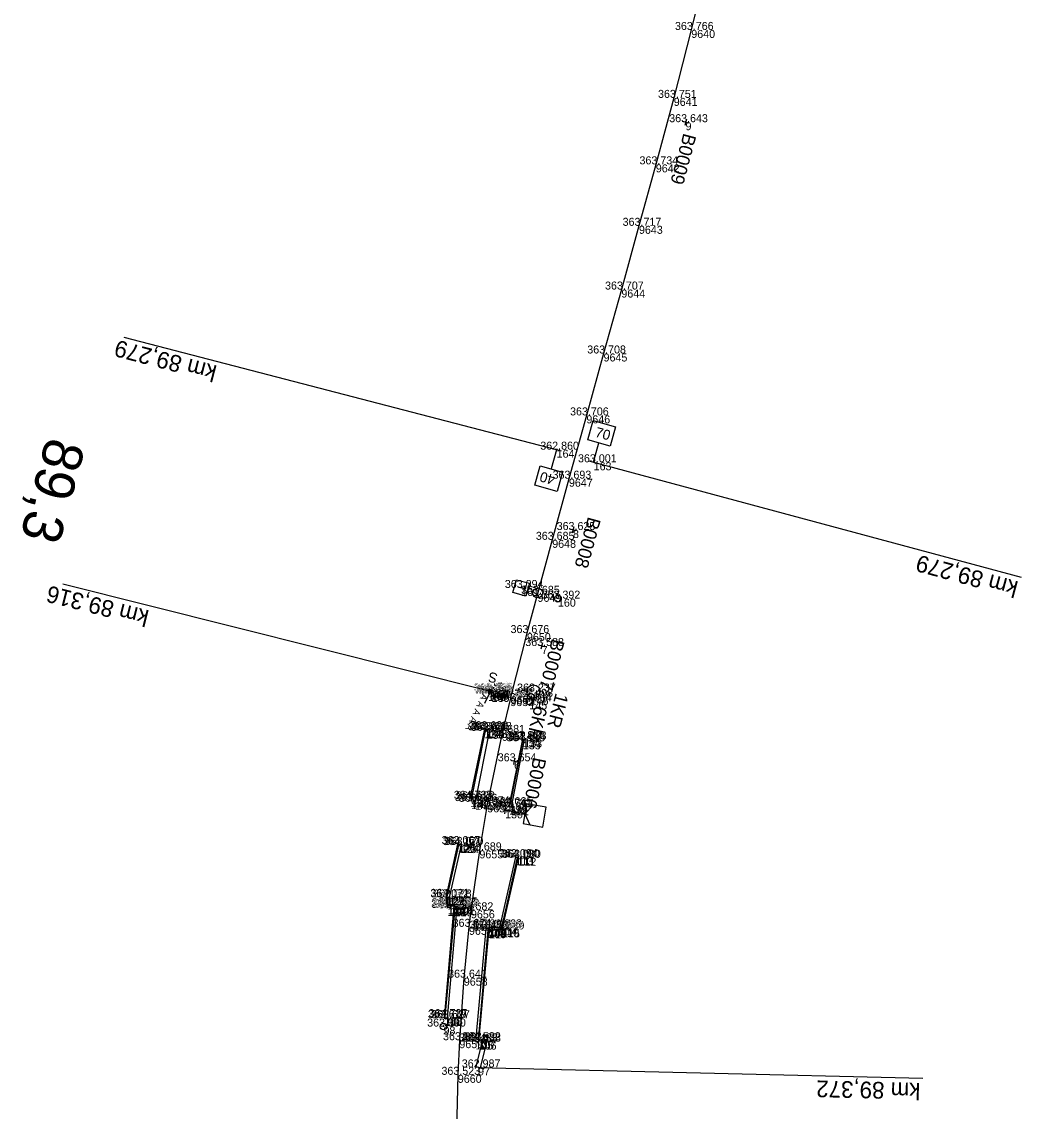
# Model space of a CAD drawing. Extents: x -599511 to -595511, y -1067427 to -1062061.
# Drawn here: x -595742.8 to -595592.8, y -1067096.5 to -1066933.1 of the extents above; entities that cross this region are included whole.
import ezdxf

# ---------------------------------------------------------------- set-up
doc = ezdxf.new("R2010")
doc.units = 0
for name, color, linetype in [('Vrstva 1', 7, 'Continuous'), ('Vrstva 12', 7, 'Continuous'), ('Vrstva 17', 7, 'Continuous'), ('Vrstva 18', 7, 'Continuous'), ('Vrstva 27', 7, 'Continuous'), ('Vrstva 33', 7, 'Continuous'), ('Vrstva 43', 7, 'Continuous'), ('Vrstva 49', 7, 'Continuous'), ('Vrstva 5', 7, 'Continuous'), ('Vrstva 50', 7, 'Continuous'), ('Vrstva 6', 7, 'Continuous'), ('Vrstva 60', 7, 'Continuous'), ('Vrstva 61', 7, 'Continuous'), ('Vrstva 7', 7, 'Continuous')]:
    doc.layers.add(name, color=color, linetype=linetype)

msp = doc.modelspace()

# ---------------------------------------------------------------- linework, layer by layer
at = {"layer": 'Vrstva 1'}
msp.add_lwpolyline([(-595640.14, -1066925.35), (-595642.33, -1066934.34), (-595644.96, -1066944.53), (-595647.65, -1066954.5), (-595650.18, -1066963.72), (-595652.82, -1066973.28), (-595655.49, -1066982.87), (-595658.07, -1066992.16), (-595660.69, -1067001.65), (-595663.2, -1067010.82), (-595665.41, -1067018.92), (-595666.99, -1067024.81), (-595669.42, -1067034.28), (-595669.48, -1067034.56), (-595670.73, -1067039.78), (-595672.94, -1067050.5), (-595674.12, -1067057.4), (-595675.39, -1067066.39), (-595675.69, -1067068.87), (-595676.46, -1067076.5), (-595677.13, -1067085.88), (-595677.36, -1067091.07), (-595677.54, -1067099.36)], dxfattribs=at)
at = {"layer": 'Vrstva 12'}
for p, q in [((-595672.83, -1067033.8), (-595672.83, -1067033.8)), ((-595672.7, -1067033.24), (-595672.7, -1067033.24)), ((-595672.14, -1067033.37), (-595672.14, -1067033.37)), ((-595672.29, -1067033.93), (-595672.28, -1067033.93))]:
    msp.add_line(p, q, dxfattribs=at)
for points in [[(-595672.7, -1067033.24), (-595672.83, -1067033.8), (-595672.28, -1067033.93), (-595672.14, -1067033.37)], [(-595672.7, -1067033.24), (-595672.83, -1067033.8), (-595672.29, -1067033.93), (-595672.14, -1067033.37)]]:
    msp.add_lwpolyline(points, close=True, dxfattribs=at)
at = {"layer": 'Vrstva 17'}
for p, q in [((-595669.51, -1067050.63), (-595667.6, -1067041.04)), ((-595677.83, -1067066.09), (-595679.29, -1067082.42)), ((-595678.84, -1067065.79), (-595677.76, -1067065.66)), ((-595674.28, -1067085.88), (-595672.79, -1067069.37))]:
    msp.add_line(p, q, dxfattribs=at)
for points in [[(-595675.16, -1067049.76), (-595675.51, -1067049.67), (-595673.38, -1067039.4), (-595673.04, -1067039.47)], [(-595677.25, -1067056.61), (-595679, -1067064.38), (-595678.84, -1067065.79)], [(-595672.79, -1067069.31), (-595670.83, -1067069.2), (-595668.43, -1067058.47)]]:
    msp.add_lwpolyline(points, dxfattribs=at)
at = {"layer": 'Vrstva 18'}
for p, q in [((-595673.15, -1067069.15), (-595674.72, -1067086.07)), ((-595674.23, -1067086.09), (-595672.68, -1067069.19)), ((-595672.68, -1067069.19), (-595673.15, -1067069.15)), ((-595674.72, -1067086.07), (-595674.23, -1067086.09))]:
    msp.add_line(p, q, dxfattribs=at)
for points in [[(-595673.15, -1067039.23), (-595672.61, -1067039.34), (-595674.77, -1067050.12), (-595675.34, -1067050.01)], [(-595669.67, -1067050.83), (-595667.62, -1067040.71), (-595667.4, -1067040.76), (-595669.36, -1067050.94)], [(-595677.34, -1067056.46), (-595676.88, -1067056.58), (-595678.65, -1067064.45), (-595678.44, -1067065.97), (-595678.9, -1067066.03), (-595679.12, -1067064.45)], [(-595679.41, -1067082.55), (-595678.91, -1067082.58), (-595677.47, -1067065.86), (-595677.94, -1067065.82)]]:
    msp.add_lwpolyline(points, close=True, dxfattribs=at)
msp.add_lwpolyline([(-595672.64, -1067069.43), (-595670.72, -1067069.26), (-595668.26, -1067058.52), (-595668.73, -1067058.42), (-595671.09, -1067068.95), (-595672.65, -1067068.99), (-595672.64, -1067069.43)], dxfattribs=at)
at = {"layer": 'Vrstva 27'}
for p, q in [((-595666.62, -1067035), (-595666.64, -1067035.1)), ((-595666.42, -1067034.32), (-595666.44, -1067034.41))]:
    msp.add_line(p, q, dxfattribs=at)
for centre in [(-595666.63, -1067035.05), (-595666.43, -1067034.37)]:
    msp.add_circle(centre, 0.5, dxfattribs=at)
at = {"layer": 'Vrstva 33'}
for p, q in [((-595667.38, -1067018.17), (-595668.35, -1067017.91)), ((-595667.25, -1067017.69), (-595667.51, -1067018.65))]:
    msp.add_line(p, q, dxfattribs=at)
msp.add_lwpolyline([(-595666.63, -1067017.34), (-595667.16, -1067019.27), (-595669.09, -1067018.74), (-595668.56, -1067016.81), (-595666.63, -1067017.34)], dxfattribs=at)
at = {"layer": 'Vrstva 43'}
msp.add_circle((-595666.02, -1067033.58), 1, dxfattribs=at)
at = {"layer": 'Vrstva 49'}
for p, q in [((-595672.21, -1067033.46), (-595672.63, -1067033.72)), ((-595672.55, -1067033.38), (-595672.29, -1067033.8))]:
    msp.add_line(p, q, dxfattribs=at)
at = {"layer": 'Vrstva 5'}
for p, q in [((-595662.54, -1066997.3), (-595727.44, -1066980.47)), ((-595662.54, -1066997.3), (-595663.34, -1067000.19)), ((-595661.81, -1066997.5), (-595663.26, -1066997.1)), ((-595656.98, -1066999.19), (-595656.18, -1066996.29)), ((-595657.7, -1066998.99), (-595656.25, -1066999.39)), ((-595656.98, -1066999.19), (-595592.82, -1067016.44))]:
    msp.add_line(p, q, dxfattribs=at)
for points in [[(-595654.49, -1066996.76), (-595657.86, -1066995.83), (-595657.07, -1066992.94), (-595653.69, -1066993.87)], [(-595665.02, -1066999.73), (-595661.65, -1067000.66), (-595662.45, -1067003.55), (-595665.82, -1067002.62)]]:
    msp.add_lwpolyline(points, close=True, dxfattribs=at)
at = {"layer": 'Vrstva 50'}
msp.add_line((-595679.5, -1067083.78), (-595679.51, -1067083.88), dxfattribs=at)
msp.add_circle((-595679.51, -1067083.83), 0.5, dxfattribs=at)
at = {"layer": 'Vrstva 6'}
for p, q in [((-595672.48, -1067033.55), (-595736.65, -1067017.48)), ((-595673.33, -1067035.34), (-595672.48, -1067033.55)), ((-595672.03, -1067033.77), (-595672.94, -1067033.34)), ((-595673.18, -1067086.66), (-595673.62, -1067085.94)), ((-595673.05, -1067086.15), (-595673.49, -1067085.42)), ((-595672.92, -1067085.63), (-595673.26, -1067085.08)), ((-595673.86, -1067086.99), (-595673.88, -1067086.96)), ((-595673.35, -1067087.11), (-595673.75, -1067086.45)), ((-595674.32, -1067089.96), (-595607.59, -1067091.59)), ((-595674.03, -1067090.04), (-595673.45, -1067090.18))]:
    msp.add_line(p, q, dxfattribs=at)
msp.add_lwpolyline([(-595674.61, -1067089.89), (-595673.39, -1067085.04), (-595672.81, -1067085.19), (-595674.03, -1067090.04), (-595674.61, -1067089.89)], dxfattribs=at)
msp.add_lwpolyline([(-595672.81, -1067085.19), (-595673.3, -1067087.13), (-595673.88, -1067086.98), (-595673.39, -1067085.04)], close=True, dxfattribs=at)
at = {"layer": 'Vrstva 60'}
for p, q in [((-595642.33, -1066934.34), (-595642.33, -1066934.34)), ((-595644.96, -1066944.53), (-595644.96, -1066944.53)), ((-595643.19, -1066948.18), (-595643.19, -1066948.18)), ((-595647.65, -1066954.5), (-595647.65, -1066954.5)), ((-595650.18, -1066963.72), (-595650.18, -1066963.72)), ((-595652.82, -1066973.28), (-595652.82, -1066973.28)), ((-595655.49, -1066982.87), (-595655.49, -1066982.87)), ((-595658.07, -1066992.16), (-595658.07, -1066992.16)), ((-595662.54, -1066997.3), (-595662.54, -1066997.3)), ((-595656.98, -1066999.19), (-595656.98, -1066999.19)), ((-595660.69, -1067001.65), (-595660.69, -1067001.65)), ((-595663.2, -1067010.82), (-595663.2, -1067010.82)), ((-595660.08, -1067009.35), (-595660.08, -1067009.35)), ((-595667.86, -1067018.04), (-595667.86, -1067018.04)), ((-595665.41, -1067018.92), (-595665.41, -1067018.92)), ((-595662.34, -1067019.65), (-595662.34, -1067019.65)), ((-595666.99, -1067024.81), (-595666.99, -1067024.81)), ((-595664.78, -1067026.75), (-595664.78, -1067026.75)), ((-595672.83, -1067033.8), (-595672.83, -1067033.8)), ((-595672.83, -1067033.8), (-595672.83, -1067033.8)), ((-595672.7, -1067033.24), (-595672.7, -1067033.24)), ((-595672.7, -1067033.24), (-595672.7, -1067033.24)), ((-595672.48, -1067033.55), (-595672.48, -1067033.55)), ((-595672.42, -1067033.59), (-595672.42, -1067033.59)), ((-595672.14, -1067033.37), (-595672.14, -1067033.37)), ((-595672.14, -1067033.37), (-595672.14, -1067033.37)), ((-595666.02, -1067033.58), (-595666.02, -1067033.58)), ((-595672.29, -1067033.93), (-595672.29, -1067033.93)), ((-595672.28, -1067033.93), (-595672.28, -1067033.93)), ((-595669.48, -1067034.56), (-595669.48, -1067034.56)), ((-595669.42, -1067034.28), (-595669.42, -1067034.28)), ((-595666.63, -1067035.05), (-595666.63, -1067035.05)), ((-595666.43, -1067034.37), (-595666.43, -1067034.37)), ((-595673.38, -1067039.4), (-595673.38, -1067039.4)), ((-595673.15, -1067039.23), (-595673.15, -1067039.23)), ((-595673.04, -1067039.47), (-595673.04, -1067039.47)), ((-595672.61, -1067039.34), (-595672.61, -1067039.34)), ((-595670.73, -1067039.78), (-595670.73, -1067039.78)), ((-595667.62, -1067040.71), (-595667.62, -1067040.71)), ((-595667.6, -1067041.04), (-595667.6, -1067041.04)), ((-595667.4, -1067040.76), (-595667.4, -1067040.76)), ((-595668.92, -1067044.04), (-595668.92, -1067044.04)), ((-595675.51, -1067049.67), (-595675.51, -1067049.67)), ((-595675.34, -1067050.01), (-595675.34, -1067050.01)), ((-595675.16, -1067049.76), (-595675.16, -1067049.76)), ((-595674.77, -1067050.12), (-595674.77, -1067050.12)), ((-595672.94, -1067050.5), (-595672.94, -1067050.5)), ((-595670.27, -1067051.4), (-595670.27, -1067051.4)), ((-595669.67, -1067050.83), (-595669.67, -1067050.83)), ((-595669.51, -1067050.63), (-595669.51, -1067050.63)), ((-595669.36, -1067050.94), (-595669.36, -1067050.94)), ((-595677.34, -1067056.46), (-595677.34, -1067056.46)), ((-595677.25, -1067056.61), (-595677.25, -1067056.61)), ((-595676.88, -1067056.58), (-595676.88, -1067056.58)), ((-595674.12, -1067057.4), (-595674.12, -1067057.4)), ((-595668.73, -1067058.42), (-595668.73, -1067058.42)), ((-595668.43, -1067058.47), (-595668.43, -1067058.47)), ((-595668.26, -1067058.52), (-595668.26, -1067058.52)), ((-595679.12, -1067064.45), (-595679.12, -1067064.45)), ((-595679, -1067064.38), (-595679, -1067064.38)), ((-595678.65, -1067064.45), (-595678.65, -1067064.45)), ((-595678.9, -1067066.03), (-595678.9, -1067066.03)), ((-595678.84, -1067065.79), (-595678.84, -1067065.79)), ((-595678.44, -1067065.97), (-595678.44, -1067065.97)), ((-595677.94, -1067065.82), (-595677.94, -1067065.82)), ((-595677.83, -1067066.09), (-595677.83, -1067066.09)), ((-595677.76, -1067065.66), (-595677.76, -1067065.66)), ((-595677.47, -1067065.86), (-595677.47, -1067065.86)), ((-595675.39, -1067066.39), (-595675.39, -1067066.39)), ((-595675.69, -1067068.87), (-595675.69, -1067068.87)), ((-595673.15, -1067069.15), (-595673.15, -1067069.15)), ((-595672.79, -1067069.31), (-595672.79, -1067069.31)), ((-595672.79, -1067069.37), (-595672.79, -1067069.37)), ((-595672.68, -1067069.19), (-595672.68, -1067069.19)), ((-595672.65, -1067068.99), (-595672.65, -1067068.99)), ((-595672.64, -1067069.43), (-595672.64, -1067069.43)), ((-595671.09, -1067068.95), (-595671.09, -1067068.95)), ((-595670.83, -1067069.2), (-595670.83, -1067069.2)), ((-595670.72, -1067069.26), (-595670.72, -1067069.26)), ((-595676.46, -1067076.5), (-595676.46, -1067076.5)), ((-595679.41, -1067082.55), (-595679.41, -1067082.55)), ((-595679.29, -1067082.42), (-595679.29, -1067082.42)), ((-595678.91, -1067082.58), (-595678.91, -1067082.58)), ((-595679.51, -1067083.83), (-595679.51, -1067083.83)), ((-595677.13, -1067085.88), (-595677.13, -1067085.88)), ((-595674.72, -1067086.07), (-595674.72, -1067086.07)), ((-595674.28, -1067085.88), (-595674.28, -1067085.88)), ((-595674.23, -1067086.09), (-595674.23, -1067086.09)), ((-595674.32, -1067089.96), (-595674.32, -1067089.96)), ((-595677.36, -1067091.07), (-595677.36, -1067091.07))]:
    msp.add_line(p, q, dxfattribs=at)
at = {"layer": 'Vrstva 7'}
for p, q in [((-595642.71, -1066948.31), (-595643.67, -1066948.05)), ((-595643.06, -1066947.7), (-595643.32, -1066948.66)), ((-595659.6, -1067009.48), (-595660.56, -1067009.22)), ((-595659.95, -1067008.87), (-595660.21, -1067009.83)), ((-595662.33, -1067019.6), (-595662.35, -1067019.7)), ((-595664.3, -1067026.87), (-595665.27, -1067026.63)), ((-595664.66, -1067026.26), (-595664.91, -1067027.23)), ((-595668.82, -1067043.55), (-595669.02, -1067044.53)), ((-595668.43, -1067044.15), (-595669.41, -1067043.94)), ((-595670.19, -1067050.91), (-595670.35, -1067051.9)), ((-595667.31, -1067051.91), (-595670.27, -1067051.4))]:
    msp.add_line(p, q, dxfattribs=at)
for points in [[(-595667.31, -1067051.91), (-595667.57, -1067053.39), (-595664.61, -1067053.9), (-595664.1, -1067050.94), (-595667.06, -1067050.43), (-595667.31, -1067051.91)], [(-595666.07, -1067050.6), (-595667.31, -1067051.91), (-595666.58, -1067053.56)]]:
    msp.add_lwpolyline(points, dxfattribs=at)
for centre, radius in [((-595665.38, -1067018.79), 0.75), ((-595662.34, -1067019.65), 0.5)]:
    msp.add_circle(centre, radius, dxfattribs=at)

# ---------------------------------------------------------------- texts
at = {"layer": 'Vrstva 27'}
for s, rotation, p in [('1KR', 255.6438, (-595662.67, -1067033.7)), ('6KR', 256.6208, (-595665.85, -1067035.63))]:
    msp.add_text(s, height=2, rotation=rotation, dxfattribs=at).set_placement(p)
at = {"layer": 'Vrstva 5'}
for s, height, rotation, p in [('km 89,279', 2.5, 165.4618, (-595713.36, -1066984.72)), ('70', 1.5, 344.5811, (-595656.86, -1066995.33)), ('40', 1.5, 164.5811, (-595662.65, -1067001.16)), ('km 89,279', 2.5, 164.9478, (-595593.11, -1067017.1))]:
    msp.add_text(s, height=height, rotation=rotation, dxfattribs=at).set_placement(p)
at = {"layer": 'Vrstva 6'}
for s, height, rotation, p in [('km 89,316', 2.5, 165.9379, (-595723.55, -1067021.44)), ('S', 1.5, 166.6122, (-595671.28, -1067030.92)), ('  A A A A A ', 1, 244.7434, (-595673.39, -1067033.13)), ('km 89,372', 2.5, 178.6042, (-595607.93, -1067092.29))]:
    msp.add_text(s, height=height, rotation=rotation, dxfattribs=at).set_placement(p)
at = {"layer": 'Vrstva 60'}
for s, p in [('9640', (-595642.33, -1066935.54)), ('9641', (-595644.96, -1066945.73)), ('9', (-595643.19, -1066949.38)), ('9642', (-595647.65, -1066955.7)), ('9643', (-595650.18, -1066964.92)), ('9644', (-595652.82, -1066974.48)), ('9645', (-595655.49, -1066984.07)), ('9646', (-595658.07, -1066993.35)), ('164', (-595662.54, -1066998.5)), ('163', (-595656.98, -1067000.39)), ('9647', (-595660.69, -1067002.85)), ('8', (-595660.08, -1067010.55)), ('9648', (-595663.2, -1067012.02)), ('161', (-595667.86, -1067019.24)), ('9649', (-595665.41, -1067020.12)), ('160', (-595662.34, -1067020.85)), ('9650', (-595666.99, -1067026.01)), ('7', (-595664.78, -1067027.95)), ('156', (-595672.83, -1067035)), ('155', (-595672.83, -1067035)), ('154', (-595672.7, -1067034.44)), ('153', (-595672.7, -1067034.44)), ('157', (-595672.48, -1067034.75)), ('158', (-595672.42, -1067034.79)), ('152', (-595672.14, -1067034.57)), ('151', (-595672.14, -1067034.57)), ('148', (-595666.02, -1067034.78)), ('149', (-595672.29, -1067035.13)), ('150', (-595672.28, -1067035.13)), ('9652', (-595669.48, -1067035.76)), ('9651', (-595669.42, -1067035.48)), ('145', (-595666.63, -1067036.25)), ('146', (-595666.43, -1067035.57)), ('138', (-595673.38, -1067040.6)), ('144', (-595673.15, -1067040.43)), ('139', (-595673.04, -1067040.67)), ('143', (-595672.61, -1067040.54)), ('9653', (-595670.73, -1067040.98)), ('134', (-595667.62, -1067041.91)), ('135', (-595667.6, -1067042.24)), ('133', (-595667.4, -1067041.96)), ('6', (-595668.92, -1067045.24)), ('137', (-595675.51, -1067050.87)), ('142', (-595675.34, -1067051.21)), ('140', (-595675.16, -1067050.96)), ('141', (-595674.77, -1067051.32)), ('9654', (-595672.94, -1067051.7)), ('130', (-595670.27, -1067052.6)), ('132', (-595669.67, -1067052.03)), ('136', (-595669.51, -1067051.83)), ('131', (-595669.36, -1067052.14)), ('125', (-595677.34, -1067057.66)), ('123', (-595677.25, -1067057.81)), ('124', (-595676.88, -1067057.78)), ('9655', (-595674.12, -1067058.6)), ('113', (-595668.73, -1067059.62)), ('111', (-595668.43, -1067059.67)), ('112', (-595668.26, -1067059.72)), ('127', (-595679.12, -1067065.65)), ('122', (-595679, -1067065.58)), ('126', (-595678.65, -1067065.65)), ('128', (-595678.9, -1067067.23)), ('121', (-595678.84, -1067066.99)), ('129', (-595678.44, -1067067.17)), ('102', (-595677.94, -1067067.02)), ('119', (-595677.83, -1067067.29)), ('120', (-595677.76, -1067066.86)), ('101', (-595677.47, -1067067.06)), ('9656', (-595675.39, -1067067.59)), ('9657', (-595675.69, -1067070.07)), ('104', (-595673.15, -1067070.35)), ('109', (-595672.79, -1067070.52)), ('108', (-595672.79, -1067070.57)), ('103', (-595672.68, -1067070.39)), ('116', (-595672.65, -1067070.19)), ('117', (-595672.64, -1067070.62)), ('114', (-595671.09, -1067070.15)), ('110', (-595670.83, -1067070.4)), ('115', (-595670.72, -1067070.46)), ('9658', (-595676.46, -1067077.7)), ('100', (-595679.41, -1067083.75)), ('118', (-595679.29, -1067083.62)), ('99', (-595678.91, -1067083.78)), ('98', (-595679.51, -1067085.03)), ('9659', (-595677.13, -1067087.07)), ('105', (-595674.72, -1067087.27)), ('107', (-595674.28, -1067087.08)), ('106', (-595674.23, -1067087.29)), ('9660', (-595677.36, -1067092.27)), ('97', (-595674.32, -1067091.16))]:
    msp.add_text(s, height=1.2, dxfattribs=at).set_placement(p)
at = {"layer": 'Vrstva 61'}
for s, p in [('363.766', (-595644.78, -1066934.34)), ('363.751', (-595647.32, -1066944.53)), ('363.643', (-595645.64, -1066948.18)), ('363.734', (-595650.1, -1066954.5)), ('363.717', (-595652.63, -1066963.72)), ('363.707', (-595655.27, -1066973.28)), ('363.708', (-595657.94, -1066982.87)), ('363.706', (-595660.52, -1066992.16)), ('362.860', (-595664.99, -1066997.3)), ('363.001', (-595659.33, -1066999.19)), ('363.693', (-595663.14, -1067001.65)), ('363.625', (-595662.53, -1067009.35)), ('363.685', (-595665.66, -1067010.82)), ('363.094', (-595670.31, -1067018.04)), ('363.685', (-595667.87, -1067018.92)), ('363.392', (-595664.79, -1067019.65)), ('363.676', (-595669.45, -1067024.81)), ('363.588', (-595667.24, -1067026.75)), ('362.912', (-595675.15, -1067033.24)), ('363.313', (-595675.15, -1067033.24)), ('363.344', (-595674.59, -1067033.37)), ('363.144', (-595674.59, -1067033.37)), ('362.938', (-595675.28, -1067033.8)), ('363.338', (-595675.28, -1067033.8)), ('363.335', (-595674.94, -1067033.55)), ('363.335', (-595674.88, -1067033.59)), ('363.139', (-595674.74, -1067033.93)), ('363.341', (-595674.64, -1067033.93)), ('363.678', (-595671.94, -1067034.56)), ('363.678', (-595671.87, -1067034.28)), ('363.504', (-595669.08, -1067035.05)), ('363.498', (-595668.88, -1067034.37)), ('363.237', (-595668.47, -1067033.58)), ('364.744', (-595675.83, -1067039.4)), ('363.629', (-595675.61, -1067039.23)), ('363.631', (-595675.4, -1067039.47)), ('363.618', (-595675.06, -1067039.34)), ('363.681', (-595673.08, -1067039.78)), ('362.848', (-595670.07, -1067040.71)), ('364.115', (-595670.06, -1067041.04)), ('362.833', (-595669.85, -1067040.76)), ('363.654', (-595671.37, -1067044.04)), ('364.735', (-595677.97, -1067049.67)), ('363.622', (-595677.61, -1067049.76)), ('363.616', (-595677.8, -1067050.01)), ('363.606', (-595677.22, -1067050.12)), ('363.674', (-595675.39, -1067050.5)), ('363.138', (-595672.72, -1067051.4)), ('362.741', (-595672.03, -1067050.83)), ('364.085', (-595671.97, -1067050.63)), ('362.767', (-595671.81, -1067050.94)), ('363.067', (-595679.79, -1067056.46)), ('364.171', (-595679.61, -1067056.61)), ('363.070', (-595679.33, -1067056.58)), ('363.689', (-595676.58, -1067057.4)), ('363.094', (-595671.18, -1067058.42)), ('364.190', (-595670.88, -1067058.47)), ('363.080', (-595670.71, -1067058.52)), ('363.071', (-595681.48, -1067064.45)), ('364.182', (-595681.45, -1067064.38)), ('363.078', (-595681.1, -1067064.45)), ('363.067', (-595681.35, -1067066.03)), ('364.178', (-595681.29, -1067065.79)), ('363.079', (-595680.9, -1067065.97)), ('363.575', (-595680.4, -1067065.82)), ('364.687', (-595680.28, -1067066.09)), ('364.175', (-595680.22, -1067065.66)), ('363.599', (-595679.93, -1067065.86)), ('363.682', (-595677.84, -1067066.39)), ('363.674', (-595678.14, -1067068.87)), ('363.453', (-595675.6, -1067069.15)), ('364.189', (-595675.24, -1067069.31)), ('364.552', (-595675.23, -1067069.37)), ('363.453', (-595675.13, -1067069.19)), ('363.064', (-595675.1, -1067068.99)), ('363.068', (-595673.55, -1067068.95)), ('364.187', (-595673.28, -1067069.2)), ('363.059', (-595673.17, -1067069.26)), ('363.066', (-595675.1, -1067069.43)), ('363.641', (-595678.82, -1067076.5)), ('364.737', (-595681.74, -1067082.42)), ('363.390', (-595681.96, -1067083.83)), ('363.619', (-595681.86, -1067082.55)), ('363.627', (-595681.36, -1067082.58)), ('363.563', (-595679.58, -1067085.88)), ('363.433', (-595677.17, -1067086.07)), ('364.532', (-595676.73, -1067085.88)), ('363.438', (-595676.69, -1067086.09)), ('362.987', (-595676.77, -1067089.96)), ('363.523', (-595679.82, -1067091.07))]:
    msp.add_text(s, height=1.2, dxfattribs=at).set_placement(p)
at = {"layer": 'Vrstva 7'}
for s, height, rotation, p in [('B0009', 2, 254.9113, (-595643.48, -1066949.73)), ('89,3', 6, 254.9869, (-595739.01, -1066995.21)), ('B0008', 2, 254.655, (-595657.81, -1067007.27)), ('B0007', 2, 255.6438, (-595663.24, -1067025.56)), ('B0006', 2, 258.337, (-595666.03, -1067043.34))]:
    msp.add_text(s, height=height, rotation=rotation, dxfattribs=at).set_placement(p)

doc.saveas('drawing.dxf')
